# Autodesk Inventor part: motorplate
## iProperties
Created: 2010-02
Part Number: motorplate
Document SubType Name: Modeling
Designer: a31883
Density: 1 g/cm^3
Author: a31883
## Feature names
1. Extrusion1
2. Extrusion2
3. Extrusion3
